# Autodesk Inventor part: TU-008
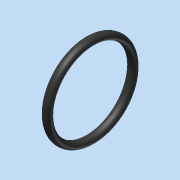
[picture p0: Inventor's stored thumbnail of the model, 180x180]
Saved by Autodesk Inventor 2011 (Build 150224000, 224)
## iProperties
Created: 2009-11
Part Number: TU-008
Material: Rubber
Document SubType Name: Modeling
Designer: t_jahrl
Density: 0.93 g/cm^3
Description: Piston O-ring
Mass: 1.05024 g
Surface Area: 13.1761 cm^2
Volume: 1.12929 cm^3
Author: t_jahrl
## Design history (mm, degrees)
sketch "Sketch1"
  geometry: L1 (-13.585, 0)-(13.585, 0) reference; L2 (-9.704, 20.425)-(9.704, 20.425); L3 (-9.704, 20.4)-(-2, 20.4); L4 (2, 20.4)-(2, 17.4); L5 (2, 17.4)-(-2, 17.4); L6 (-2, 17.4)-(-2, 20.4); L7 (0, -4.085)-(0, 24.51) reference; L8 (2, 20.4)-(9.704, 20.4); L9 (-2, 18.912)-(2, 18.912); 4 further points; 1 other entity
  constraints: 14 end point, 4 parallel, 4 point on line, 3 horizontal, 3 midpoint, 3 perpendicular, 1 collinear, 4 other
  dimensions: "d0" = 40.85 diameter of L2 L1; "d2" = 40.8 diameter of L8 L1; "d3" = 4 distance between parallel lines of L6 L4; "d4" = 3 distance of L4.start L4.end; "d6" = 3.025 distance between parallel lines of L5 L2 (derived); "d7" = 1.5125 distance between parallel lines of L2 L9 (= 0.5 x d6)
revolve "Revolution1" sketch "Sketch1" stored, may be unused: angle "d5" = 90 deg
body "Solid1"
